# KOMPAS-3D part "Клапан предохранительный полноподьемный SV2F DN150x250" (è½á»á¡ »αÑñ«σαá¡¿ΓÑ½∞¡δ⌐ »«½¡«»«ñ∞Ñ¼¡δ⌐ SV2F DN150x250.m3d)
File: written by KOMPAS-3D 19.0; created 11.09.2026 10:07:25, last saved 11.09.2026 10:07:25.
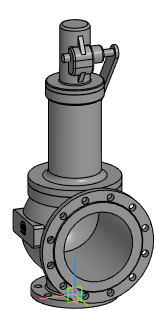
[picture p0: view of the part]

Document properties: Автор: Энергия; Полное имя файла: Z:\3.Личные\sachek\Dendor\_3D для проектировщиков\5.9 SV2F. Клапан предохранительный полноподьемный\SV2F_STP\Клапан предохранительный полноподьемный SV2F DN150x250.m3d

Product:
- Part/product: Клапан предохранительный полноподьемный SV2F DN150x250

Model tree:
1. Операция без истории:1  (labels: Клапан предохранительный полноподьемный SV2F DN150x250)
